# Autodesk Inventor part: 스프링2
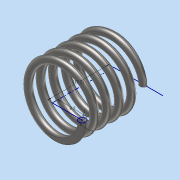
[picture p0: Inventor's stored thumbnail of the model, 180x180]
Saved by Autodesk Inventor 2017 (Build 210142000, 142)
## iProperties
Part Number: 스프링2
Material: 스테인레스 스틸
Document SubType Name: Modeling
Designer: MRC
Density: 8 g/cm^3
Appearance: 반연마
Mass: 6.55763 g
Surface Area: 16.7052 cm^2
Volume: 0.819704 cm^3
Author: MRC
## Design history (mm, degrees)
sketch "스케치1"
  geometry: L1 (0, 0)-(0, 17.5); L2 (0, 0)-(8.5, 0); L3 (0, 17.5)-(14, 17.5); C1 r 1 at (8.5, 0)
  constraints: 6 end point, 2 horizontal, 1 centre point, 1 coincident, 1 vertical
  dimensions: "d0" = 17.5 distance of L1.start L1.end (derived); "d1" = 8.5 distance of L1.start L2.end; "d2" = 2 diameter of C1
feature "코일1" sketch "스케치1" pitch "d3" = 10; turns "d5" = 5; dims "d4" = 17.5 (= d0), "d6" = 0, angle "d7" = 90 deg, angle "d8" = 90 deg, "d9" = 0, "d10" = 0
sketch "스케치2"
  geometry: L1 (17.5, 11)-(0, 11); L2 (0, 11)-(0, -11); L3 (0, -11)-(17.5, -11); L4 (17.5, -11)-(17.5, 11); 2 further points
  constraints: 8 end point, 2 parallel, 1 coincident, 1 horizontal, 1 midpoint, 1 perpendicular
  dimensions: "d11" = 17.5 distance of L2.end L3.end (= d0); "d12" = 22 distance between parallel lines of L3 L1
extrude "돌출1" sketch "스케치2" stored distance "d13" = 50; taper "d14" = 0 deg
node "솔리드1"
